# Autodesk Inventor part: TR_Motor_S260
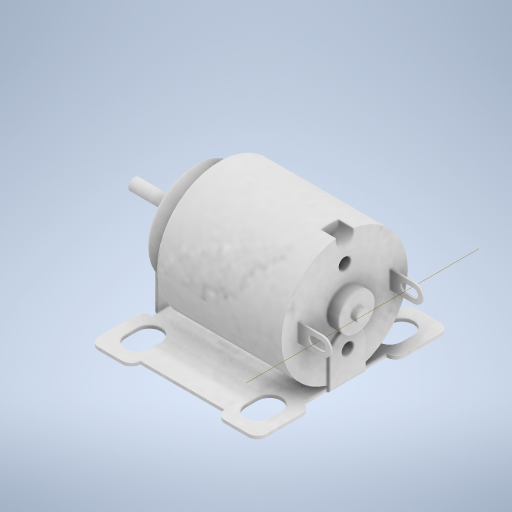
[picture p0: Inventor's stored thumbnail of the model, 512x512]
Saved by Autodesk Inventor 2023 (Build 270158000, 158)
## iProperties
Created: 2023-11
Part Number: TR_Motor_S260
Material: Stahl, Legierung
Document SubType Name: Modeling
Designer: Greiner
Density: 7.73 g/cm^3
Appearance: Geglättet - Grau
Author: Greiner
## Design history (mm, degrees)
sketch "Skizze1"
  geometry: L1 (38, 0)-(38, -1); L2 (38, -1)-(29.8, -1); L3 (29.8, -1)-(29.8, -3); L4 (29.8, -3)-(28, -3); L5 (28, -3)-(28, -8); L6 (28, -8)-(24, -8); L7 (24, -8)-(24, -10.5); L8 (24, -10.5)-(3, -10.5); L9 (3, -10.5)-(3, -3); L10 (3, -3)-(1, -3); L11 (1, -3)-(1, -1); L12 (1, -1)-(0, -1); L13 (0, -1)-(0, 0); L14 (38, 0)-(0, 0); 2 further points
  constraints: 28 end point, 8 perpendicular, 4 point on line, 2 horizontal, 2 horizontal alignment, 1 coincident, 1 midpoint, 1 parallel, 1 vertical
  dimensions: "d0" = 2 diameter of point (33.9, -1) L14; "d1" = 6 diameter of L4 L14; "d2" = 16 diameter of L6 L14; "d3" = 21 diameter of L8 L14; "d5" = 35 horizontal distance of L1.start L9.end; "d6" = 26.8 horizontal distance of L2.end L9.end; "d7" = 25 distance of L4.end L9.end; "d8" = 21 horizontal distance of L6.end L9.end; "d9" = 2 distance of L10.end L9.end; "d10" = 3 horizontal distance of L12.end L9.end
revolve "Umdrehung1" sketch "Skizze1" stored, may be unused: angle "d11" = 90 deg
sketch "Skizze2"
  geometry: C1 r 1 at (0, 6); C2 r 1.5 at (0, 10); 1 further point
  constraints: 2 centre point, 2 vertical alignment
  dimensions: "d12" = 3 diameter of C2; "d13" = 2 diameter of C1; "d14" = 6 distance of point (0, 0) C1.centre; "d15" = 10 distance of point (0, 0) C2.centre
extrude "Extrusion1" cut sketch "Skizze2" distance "d16" = 2.5; taper "d17" = 0 deg
mirror "Spiegeln1"
workplane "Arbeitsebene1"
sketch "Skizze3"
  geometry: L1 (-3, -3)-(-3, 3) reference; L2 (-3, 1.5)-(1, 1.5); L3 (-3, -1.5)-(1, -1.5); L4 (1, 0)-(-0.5, 0); L5 (1, -0.75)-(-0.5, -0.75); L6 (-0.5, 0.75)-(1, 0.75); L7 (-1, -3)-(-1, 3) reference; A1 r 1.5 centre (1, 0) between (1, -1.5) and (1, 1.5); A2 r 0.75 centre (1, 0) between (1, -0.75) and (1, 0.75); A3 r 0.75 centre (-0.5, 0) between (-0.5, 0.75) and (-0.5, -0.75); 2 further points
  constraints: 12 end point, 6 point on circle, 6 tangent, 3 centre point, 3 horizontal, 2 point on line, 1 coincident, 1 horizontal alignment, 1 midpoint, 1 parallel
  dimensions: "d19" = 1.5 radius of A1; "d21" = 1.5 distance of A1.centre L4.end; "d22" = 0.75 radius of A2; "d24" = 4 distance from line of L1 A1.centre
extrude "Extrusion2" join sketch "Skizze3" distance "d25" = 0.3; taper "d26" = 0 deg
mirror "Spiegeln2"
fillet "Rundung1" dims "d27" = 0.5
workplane "Arbeitsebene2"
sketch "Skizze4"
  geometry: L1 (29.5, 16)-(22.5, 16); L2 (22.5, 16)-(22.5, 14.5); L3 (22.5, 14.5)-(8.5, 14.5); L4 (8.5, 14.5)-(8.5, 16); L5 (8.5, 16)-(1.5, 16); L6 (1.5, 16)-(1.5, 7); L7 (1.5, 7)-(3, 7); L8 (3, 7)-(3, -7); L9 (3, -7)-(1.5, -7); L10 (1.5, -7)-(1.5, -16); L11 (1.5, -16)-(8.5, -16); L12 (8.5, -16)-(8.5, -14.5); L13 (8.5, -14.5)-(22.5, -14.5); L14 (22.5, -14.5)-(22.5, -16); L15 (22.5, -16)-(29.5, -16); L16 (29.5, -16)-(29.5, -7); L17 (29.5, -7)-(28, -7); L18 (28, -7)-(28, 7); L19 (28, 7)-(29.5, 7); L20 (29.5, 16)-(29.5, 7); L21 (3, -1.5)-(3, 1.5) reference; 4 further points
  constraints: 40 end point, 13 perpendicular, 13 point on line, 6 equal length, 2 midpoint, 1 horizontal, 1 vertical alignment
  dimensions: "d29" = 32 distance of L15.end L1.start; "d30" = 28 distance of L5.end L1.start; "d31" = 14 distance of L2.end L3.end; "d32" = 1.5 distance of L1.end L2.end
extrude "Extrusion3" join sketch "Skizze4" distance "d33" = 0.5; taper "d34" = 0 deg
fillet "Rundung2" dims "d35" = 1.5
sketch "Skizze5"
  geometry: L1 (14, -0.5)-(0, -0.5) reference; L2 (4, -0.5)-(4, 4.5); L3 (4, -0.5)-(10, -0.5); L4 (10, 4.5)-(10, -0.5); C1 r 0.625 at (7, 4.5); C2 r 1 at (7, 4.5) reference; A1 r 3 centre (7, 4.5) between (10, 4.5) and (4, 4.5); 1 further point
  constraints: 6 end point, 2 centre point, 2 coincident, 2 point on circle, 2 point on line, 2 tangent, 1 perpendicular, 1 vertical
  dimensions: "d36" = 3 radius of A1; "d37" = 1.25 diameter of C1
extrude "Extrusion4" join sketch "Skizze5" distance "d38" = 0.5; taper "d39" = 0 deg
sketch "Skizze6"
  geometry: L1 (10, -0.5)-(14, -0.5) reference; L2 (1, -0.5)-(1, 10.5); L3 (13, 10.5)-(13, -0.5); L4 (13, -0.5)-(1, -0.5); L5 (14, -0.5)-(0, -0.5) reference; C1 r 3.1 at (7, 10.5); A1 r 6 centre (7, 10.5) between (13, 10.5) and (1, 10.5); 3 further points
  constraints: 6 end point, 2 centre point, 2 coincident, 2 point on circle, 2 tangent, 2 vertical, 1 horizontal, 1 point on line
  dimensions: "d41" = 6 radius of A1; "d42" = 6.2 diameter of C1
extrude "Extrusion5" join sketch "Skizze6" distance "d43" = 0.5; taper "d44" = 0 deg
fillet "Rundung4" dims "d45" = 0.5
sketch "Skizze7"
  geometry: L1 (-25.5, 12)-(-25.5, 10); L2 (-23.5, 12)-(-23.5, 10); L3 (-27.5, 10)-(-27.5, 12); L4 (-24, 16)-(-28, 16) reference; L5 (-29.5, 14.5)-(-29.5, 8.5) reference; A1 r 2 centre (-25.5, 12) between (-23.5, 12) and (-27.5, 12); A2 r 2 centre (-25.5, 10) between (-27.5, 10) and (-23.5, 10); 3 further points
  constraints: 8 end point, 4 point on circle, 4 tangent, 2 centre point, 2 midpoint, 1 parallel, 1 vertical
  dimensions: "d46" = 2 distance of L1.end L1.start; "d47" = 2 radius of A1; "d48" = 4 vertical distance of point (-26, 16) L1.start; "d49" = 4 distance from line of L1.start L5
extrude "Extrusion6" cut sketch "Skizze7" extent not by distance; stored distance "d50" = 0; taper "d51" = 0 deg
pattern_linear "Rechteckige Anordnung1" dims "d54" = 20, "d57" = 22
feature "ȣ耀ȥ耀ȧ耀ȩ耀ȫ耀ȭ耀ȯ耀ȱ耀" dims "d0" = 2, "d1" = 6, "d2" = 16, "d3" = 21, "d5" = 35, "d6" = 26.8, "d7" = 25, "d8" = 21, "d9" = 2, "d10" = 3, "d11" = 90 deg, "d12" = 3, "d13" = 2, "d14" = 6, "d15" = 10, "d16" = 2.5, "d17" = 0, "d18" = 7.5, "d19" = 1.5, "d21" = 1.5, "d22" = 0.75, "d24" = 4, "d25" = 0.3, "d26" = 0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
node "Volumenkörper1"
